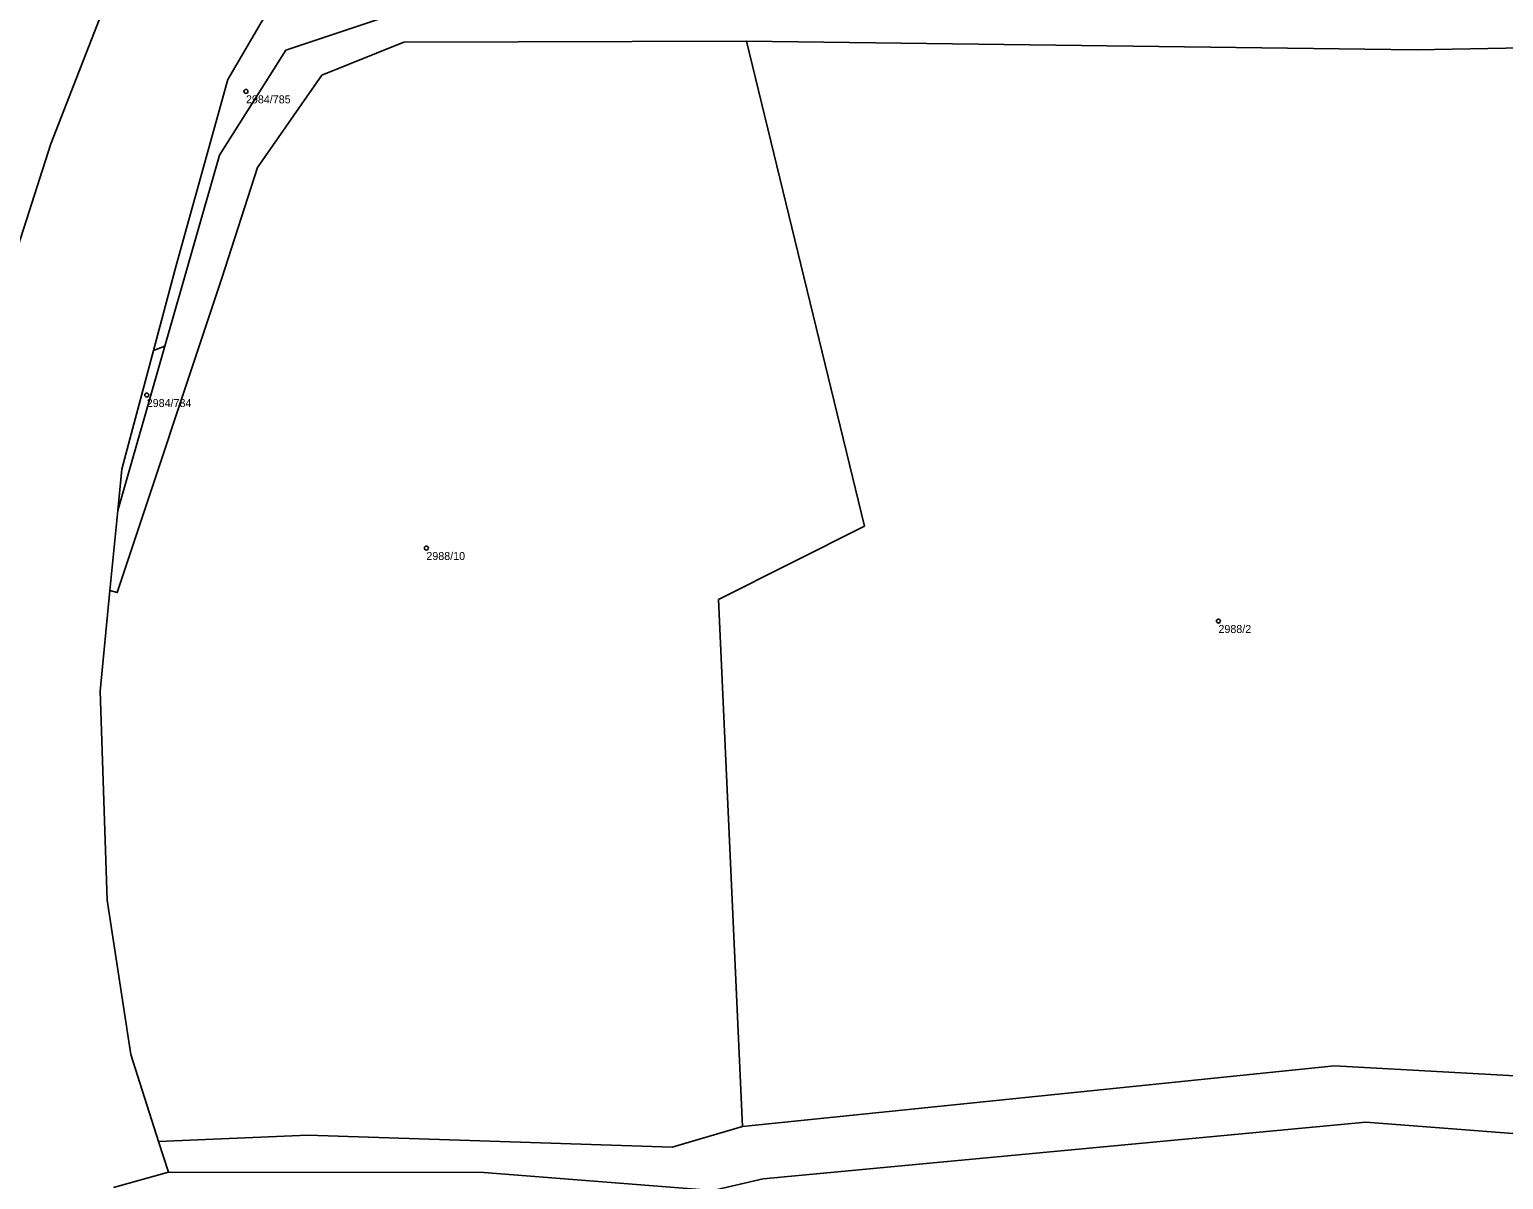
# Model space of a CAD drawing. Extents: x -878211 to -870363, y -1058464 to -1052522.
# Drawn here: x -874051.4 to -873867.2, y -1056236.7 to -1056092.9 of the extents above; entities that cross this region are included whole.
import ezdxf

# ---------------------------------------------------------------- set-up
doc = ezdxf.new("R2010")
doc.units = 0
doc.layers.add('Vrstva 50', color=7, linetype='Continuous')
doc.layers.add('Vrstva 51', color=7, linetype='Continuous')

msp = doc.modelspace()

# ---------------------------------------------------------------- linework, layer by layer
at = {"layer": 'Vrstva 50'}
for centre in [(-874024.38, -1056100.67994), (-874036.78, -1056138.62994), (-874001.84, -1056157.74994), (-873902.86, -1056166.86994)]:
    msp.add_circle(centre, 0.25, dxfattribs=at)
at = {"layer": 'Vrstva 51'}
for points in [[(-873865.37, -1055954.75), (-873878.23, -1055960.39), (-873892.52, -1055966.18), (-873911.31, -1055974.31), (-873925.46, -1055980.46), (-873932.28, -1055983.42), (-873939.2, -1055986.41), (-873946.14, -1055989.65), (-873958.05, -1055994.81), (-873966.71, -1056000.36), (-873975.38, -1056008.83), (-873989.92, -1056022.91), (-874003.01, -1056035.73), (-874039.57, -1056083.57), (-874048.77, -1056107.25), (-874057.99, -1056135.83), (-874062.23, -1056148.73), (-874064.44, -1056172.46), (-874059.65, -1056228.47), (-874059.11, -1056233.23), (-874058.08, -1056239.54)], [(-874040.92, -1056237.64), (-874034.08, -1056235.73), (-874035.3, -1056231.92), (-874038.77, -1056221.03), (-874041.72, -1056201.74), (-874042.62, -1056175.62), (-874041.38, -1056163.05), (-874040.39, -1056153.05), (-874039.88, -1056147.87), (-874035.94, -1056133.05), (-874033.12, -1056122.42), (-874026.65, -1056099.18), (-874012.21, -1056074.45), (-874005.36, -1056063.14), (-874001, -1056055.93), (-873994.02, -1056044.02), (-873976.69, -1056030.75), (-873965.62, -1056022.6), (-873960.85, -1056019.45), (-873933.34, -1056004.26), (-873896.15, -1055987.86), (-873830.39, -1055958.21)], [(-873840.34, -1056089.55), (-873878.08, -1056089.5), (-873994.8, -1056089.08), (-874000.16, -1056089.06), (-874019.41, -1056095.51), (-874027.71, -1056108.65), (-874034.52, -1056132.5), (-874040.39, -1056153.05), (-874041.38, -1056163.05), (-874040.47, -1056163.31), (-874027.4, -1056124.02), (-874022.95, -1056110.18), (-874014.9, -1056098.66), (-874004.66, -1056094.51), (-873961.82, -1056094.39), (-873878.1, -1056095.5), (-873849.14, -1056094.93)], [(-873858.28, -1056224.11), (-873888.36, -1056222.44), (-873962.33, -1056230.05), (-873971.13, -1056232.61), (-874016.67, -1056231.12), (-874035.3, -1056231.92), (-874034.08, -1056235.73), (-873994.67, -1056235.76), (-873966.06, -1056238.02), (-873959.74, -1056236.58), (-873884.44, -1056229.48), (-873855.25, -1056231.72)], [(-873966.06, -1056238.02), (-873994.67, -1056235.76), (-874034.08, -1056235.73), (-874040.92, -1056237.64)]]:
    msp.add_lwpolyline(points, dxfattribs=at)
for points in [[(-874083.99, -1056066.24), (-874080.7, -1056077.88), (-874075.33, -1056096.89), (-874092.05, -1056109.34), (-874118.47, -1056117.14), (-874116.81, -1056122.76), (-874101.89, -1056134.11), (-874098.83, -1056136.48), (-874062.01, -1056135.86), (-874057.99, -1056135.83), (-874048.77, -1056107.25), (-874039.57, -1056083.57), (-874003.01, -1056035.73), (-874020.49, -1056040.6), (-874041.66, -1056047.24), (-874050.77, -1056050.02), (-874068.35, -1056058.84)], [(-874012.08, -1056076.67), (-874006.62, -1056067.86), (-874000.4, -1056067.59), (-874001.22, -1056064.47), (-874004.25, -1056066.47), (-874005.21, -1056065.57), (-874003.6, -1056063), (-874005.36, -1056063.14), (-874012.21, -1056074.45), (-874026.65, -1056099.18), (-874033.12, -1056122.42), (-874035.94, -1056133.05), (-874034.52, -1056132.5), (-874027.71, -1056108.65), (-874019.41, -1056095.51), (-874000.16, -1056089.06), (-873994.8, -1056089.08), (-873995.12, -1056087.84), (-874008.5, -1056088.69), (-874016.88, -1056091.03), (-874020.55, -1056091.49)], [(-873965.35, -1056164.18), (-873947.09, -1056155), (-873961.82, -1056094.39), (-874004.66, -1056094.51), (-874014.9, -1056098.66), (-874022.95, -1056110.18), (-874027.4, -1056124.02), (-874040.47, -1056163.31), (-874041.38, -1056163.05), (-874042.62, -1056175.62), (-874041.72, -1056201.74), (-874038.77, -1056221.03), (-874035.3, -1056231.92), (-874016.67, -1056231.12), (-873971.13, -1056232.61), (-873962.33, -1056230.05)], [(-873849.14, -1056094.93), (-873878.1, -1056095.5), (-873961.82, -1056094.39), (-873947.09, -1056155), (-873965.35, -1056164.18), (-873962.33, -1056230.05), (-873888.36, -1056222.44), (-873858.28, -1056224.11), (-873841.07, -1056228.71), (-873838.28, -1056147.4)], [(-874034.52, -1056132.5), (-874035.94, -1056133.05), (-874039.88, -1056147.87), (-874040.39, -1056153.05)], [(-873884.44, -1056229.48), (-873959.74, -1056236.58), (-873966.06, -1056238.02), (-873949.57, -1056239.32), (-873906.89, -1056250.02), (-873863.25, -1056249.81), (-873849.46, -1056254.08), (-873808.82, -1056273.56), (-873801.68, -1056283.67), (-873783.49, -1056273.9), (-873757.98, -1056277.81), (-873789.7, -1056262.56), (-873807.42, -1056251.56), (-873813.69, -1056250.11), (-873855.25, -1056231.72)]]:
    msp.add_lwpolyline(points, close=True, dxfattribs=at)

# ---------------------------------------------------------------- texts
at = {"layer": 'Vrstva 50'}
for s, p in [('2984/785', (-874024.38, -1056102.169)), ('2984/784', (-874036.78, -1056140.119)), ('2988/10', (-874001.84, -1056159.239)), ('2988/2', (-873902.86, -1056168.359))]:
    msp.add_text(s, height=0.999996, dxfattribs=at).set_placement(p)

doc.saveas('drawing.dxf')
